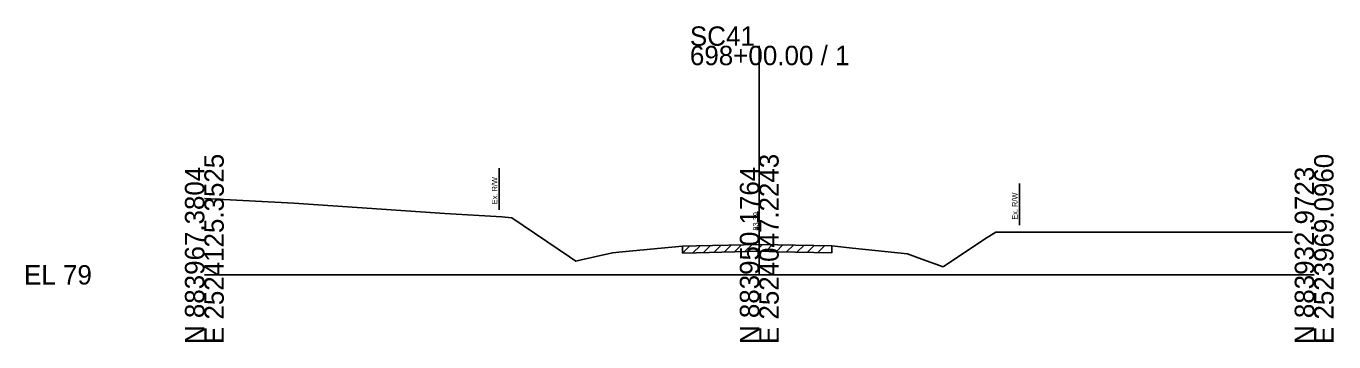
# Model space of a CAD drawing. Extents: x -26 to 183, y -10 to 24021.
# Drawn here: x -25.7 to 162.8, y 20990.3 to 21035.9 of the extents above; entities that cross this region are included whole.
import ezdxf

# ---------------------------------------------------------------- set-up
doc = ezdxf.new("R2010")
doc.units = 0
for name, color, linetype in [('RD_GPK_XS_Cell', 7, 'Continuous'), ('RD_XS_ExGround', 7, 'Continuous'), ('RD_XS_ExPaveRet', 7, 'Continuous'), ('RD_XS_ExRW', 7, 'Continuous'), ('RD_XS_TX_Elev_EX', 7, 'Continuous')]:
    doc.layers.add(name, color=color, linetype=linetype)

msp = doc.modelspace()

# ---------------------------------------------------------------- linework, layer by layer
at = {"layer": 'RD_GPK_XS_Cell'}
for p, q in [((80, 21000), (80, 21033.09)), ((0, 21000), (80, 21000)), ((80, 21000), (160, 21000))]:
    msp.add_line(p, q, dxfattribs=at)
at = {"layer": 'RD_XS_ExGround'}
for p, q in [((0, 21011.03), (12.9, 21010.35)), ((12.9, 21010.35), (34.68, 21008.87)), ((34.68, 21008.87), (42.87, 21008.39)), ((42.87, 21008.39), (44.34, 21008.21)), ((44.34, 21008.21), (52.63, 21002.6)), ((106.53, 21001.15), (112.47, 21005.17)), ((112.47, 21005.17), (114.12, 21006.14)), ((114.12, 21006.14), (118.04, 21006.18)), ((118.04, 21006.18), (122.61, 21006.16)), ((122.61, 21006.16), (139.2, 21006.18)), ((139.2, 21006.18), (156.9, 21006.14)), ((52.63, 21002.6), (53.54, 21001.98)), ((54.15, 21002.12), (58.85, 21003.17)), ((58.85, 21003.17), (60.24, 21003.32)), ((60.24, 21003.32), (68.94, 21004.13)), ((68.94, 21004.13), (70.94, 21004.18)), ((70.94, 21004.18), (80.12, 21004.4)), ((80.12, 21004.4), (82.65, 21004.34)), ((82.65, 21004.34), (90.47, 21004.18)), ((90.47, 21004.18), (93.44, 21003.87)), ((93.44, 21003.87), (101.36, 21003.01)), ((101.36, 21003.01), (102.93, 21002.45)), ((53.54, 21001.98), (54.15, 21002.12)), ((102.93, 21002.45), (106.53, 21001.15))]:
    msp.add_line(p, q, dxfattribs=at)
at = {"layer": 'RD_XS_ExPaveRet'}
for p, q in [((68.94, 21003.13), (69.96, 21004.16)), ((68.94, 21003.13), (68.94, 21004.13)), ((68.94, 21003.13), (70.94, 21003.18)), ((70.44, 21003.17), (71.46, 21004.19)), ((70.94, 21003.18), (80.12, 21003.4)), ((71.94, 21003.21), (72.96, 21004.23)), ((73.44, 21003.24), (74.46, 21004.26)), ((74.94, 21003.28), (75.96, 21004.3)), ((76.44, 21003.31), (77.46, 21004.33)), ((77.94, 21003.35), (78.96, 21004.37)), ((79.44, 21003.38), (80.45, 21004.39)), ((80.12, 21003.4), (82.65, 21003.34)), ((80.94, 21003.38), (81.92, 21004.36)), ((82.44, 21003.34), (83.42, 21004.32)), ((82.65, 21003.34), (90.47, 21003.18)), ((83.94, 21003.31), (84.92, 21004.29)), ((85.44, 21003.28), (86.42, 21004.26)), ((86.94, 21003.25), (87.92, 21004.23)), ((88.44, 21003.22), (89.42, 21004.2)), ((90.47, 21004.18), (90.47, 21003.18))]:
    msp.add_line(p, q, dxfattribs=at)
at = {"layer": 'RD_XS_ExRW'}
for p, q in [((42.5, 21015.41), (42.5, 21009.41)), ((117.5, 21013.18), (117.5, 21007.18))]:
    msp.add_line(p, q, dxfattribs=at)

# ---------------------------------------------------------------- texts
at = {"layer": 'RD_GPK_XS_Cell'}
for s, p in [('SC41', (70, 21033.09)), ('698+00.00 / 1', (70, 21030.29)), ('EL 79', (-26, 20998.6))]:
    msp.add_text(s, height=2.8, dxfattribs=at).set_placement(p)
for s, p in [('E 2524125.3525', (2.8, 20990)), ('E 2524047.2243', (82.8, 20990)), ('E 2523969.0960', (162.8, 20990)), ('N 883967.3804', (0, 20990)), ('N 883950.1764', (80, 20990)), ('N 883932.9723', (160, 20990))]:
    msp.add_text(s, height=2.8, rotation=90, dxfattribs=at).set_placement(p)
at = {"layer": 'RD_XS_ExRW'}
for p in [(42.25, 21010.2), (117.25, 21007.96)]:
    msp.add_text('Ex. R/W ', height=0.8, rotation=90, dxfattribs=at).set_placement(p)
at = {"layer": 'RD_XS_TX_Elev_EX'}
msp.add_text('83.39', height=0.8, rotation=90, dxfattribs=at).set_placement((79.9, 21006.39))

doc.saveas('drawing.dxf')
